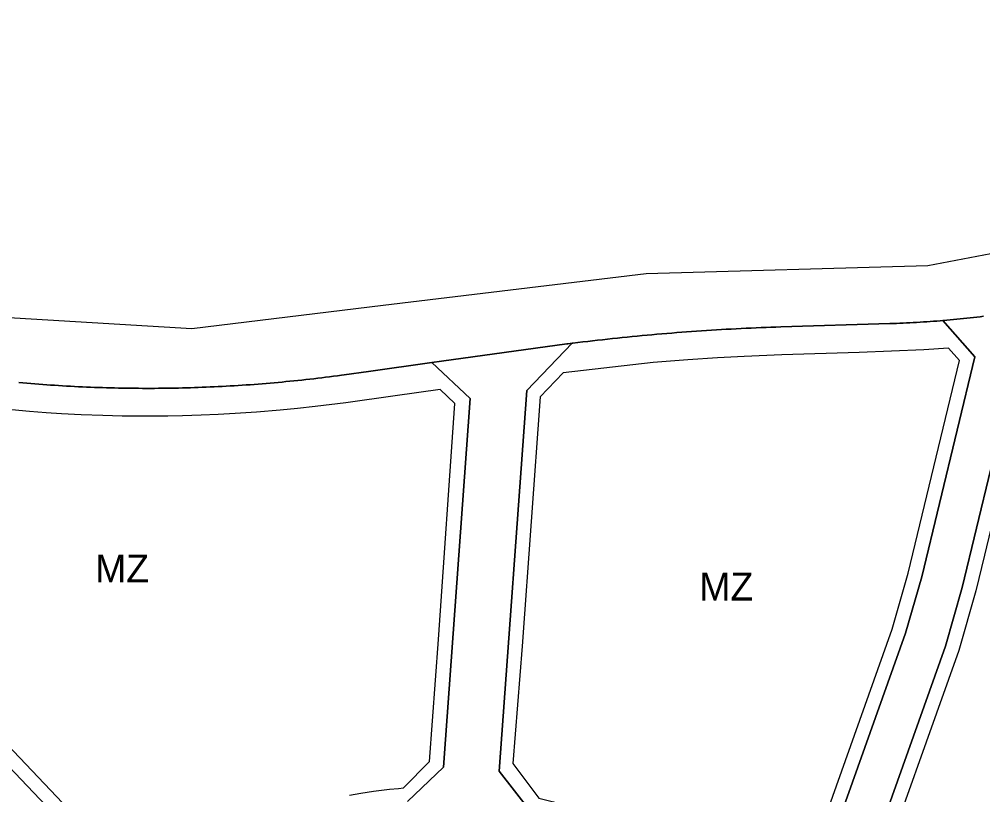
# Model space of a CAD drawing. Extents: x -297746 to -295403, y 27112 to 28877.
# Drawn here: x -297178.2 to -296833.6, y 27889.5 to 28167.1 of the extents above; entities that cross this region are included whole.
import ezdxf

# ---------------------------------------------------------------- set-up
doc = ezdxf.new("R2010")
doc.units = 0
for name, color, linetype in [('linie_rozgraniczajace', 7, 'Continuous'), ('linie_zabudowy_nieprzekraczalne', 7, 'Continuous'), ('oznaczenia_przeznaczen', 7, 'Continuous')]:
    doc.layers.add(name, color=color, linetype=linetype)

msp = doc.modelspace()

# ---------------------------------------------------------------- linework, layer by layer
at = {"layer": 'linie_rozgraniczajace'}
for points in [[(-297352.574, 28097.205), (-297275.154, 28075.397), (-297209.735, 28062.001), (-297116.494, 28056.361), (-297048.036, 28064.682), (-296954.075, 28076.102), (-296853.315, 28078.922), (-296783.197, 28092.318), (-296733.569, 28109.944), (-296648.599, 28167.051)], [(-297133.128, 27848.059), (-297348.943, 28075.477)], [(-297348.943, 28075.477), (-297133.128, 27848.059)], [(-296845.312, 28059.437), (-296846.507, 28059.33), (-296847.703, 28059.227), (-296847.897, 28059.211), (-296848.899, 28059.128), (-296850.095, 28059.033), (-296851.291, 28058.942), (-296852.488, 28058.856), (-296853.685, 28058.773), (-296854.883, 28058.694), (-296856.08, 28058.619), (-296857.278, 28058.548), (-296858.477, 28058.481), (-296859.675, 28058.418), (-296860.873, 28058.359), (-296862.072, 28058.304), (-296863.271, 28058.253), (-296864.47, 28058.206), (-296865.669, 28058.163), (-296866.869, 28058.124), (-296905.825, 28056.921), (-296907.601, 28056.864), (-296909.378, 28056.804), (-296911.154, 28056.739), (-296912.931, 28056.67), (-296914.707, 28056.597), (-296916.483, 28056.52), (-296918.259, 28056.439), (-296920.034, 28056.355), (-296921.81, 28056.266), (-296923.585, 28056.173), (-296925.36, 28056.076), (-296927.135, 28055.975), (-296928.909, 28055.871), (-296930.683, 28055.762), (-296932.458, 28055.649), (-296934.231, 28055.532), (-296936.005, 28055.412), (-296937.778, 28055.287), (-296939.551, 28055.158), (-296941.324, 28055.025), (-296943.096, 28054.889), (-296944.868, 28054.748), (-296946.64, 28054.603), (-296948.411, 28054.455), (-296950.182, 28054.302), (-296951.953, 28054.145), (-296953.724, 28053.985), (-296955.494, 28053.82), (-296957.263, 28053.651), (-296959.032, 28053.479), (-296960.801, 28053.302), (-296962.57, 28053.122), (-296964.338, 28052.937), (-296966.105, 28052.749), (-296967.873, 28052.556), (-296969.639, 28052.36), (-296971.406, 28052.159), (-296973.171, 28051.955), (-296974.937, 28051.747), (-296976.702, 28051.534), (-296978.466, 28051.318), (-296980.23, 28051.098), (-296980.47, 28051.068), (-296981.994, 28050.874), (-296982.377, 28050.824), (-297027.192, 28044.637), (-297030.725, 28044.146), (-297053.37, 28040.999), (-297062.069, 28039.791), (-297062.997, 28039.663), (-297064.412, 28039.471), (-297065.828, 28039.283), (-297067.244, 28039.098), (-297068.661, 28038.918), (-297070.079, 28038.742), (-297071.496, 28038.57), (-297072.915, 28038.402), (-297074.334, 28038.238), (-297075.753, 28038.077), (-297077.173, 28037.921), (-297078.593, 28037.769), (-297080.013, 28037.621), (-297081.434, 28037.476), (-297082.856, 28037.336), (-297084.277, 28037.2), (-297085.7, 28037.067), (-297087.122, 28036.939), (-297088.545, 28036.814), (-297089.968, 28036.694), (-297091.392, 28036.577), (-297092.815, 28036.465), (-297094.24, 28036.357), (-297095.664, 28036.252), (-297097.089, 28036.152), (-297098.514, 28036.055), (-297099.939, 28035.963), (-297101.365, 28035.874), (-297102.79, 28035.789), (-297104.216, 28035.709)], [(-296967.873, 28052.556), (-296966.105, 28052.749), (-296964.338, 28052.937), (-296962.57, 28053.122), (-296960.801, 28053.302), (-296959.032, 28053.479), (-296957.263, 28053.651), (-296955.494, 28053.82), (-296953.724, 28053.985), (-296951.953, 28054.145), (-296950.182, 28054.302), (-296948.411, 28054.455), (-296946.64, 28054.603), (-296944.868, 28054.748), (-296943.096, 28054.889), (-296941.324, 28055.025), (-296939.551, 28055.158), (-296937.778, 28055.287), (-296936.005, 28055.412), (-296934.231, 28055.532), (-296932.458, 28055.649), (-296930.683, 28055.762), (-296928.909, 28055.871), (-296927.135, 28055.975), (-296925.36, 28056.076), (-296923.585, 28056.173), (-296921.81, 28056.266), (-296920.034, 28056.355), (-296918.259, 28056.439), (-296916.483, 28056.52), (-296914.707, 28056.597), (-296912.931, 28056.67), (-296911.154, 28056.739), (-296909.378, 28056.804), (-296907.601, 28056.864), (-296905.825, 28056.921), (-296866.869, 28058.124), (-296865.669, 28058.163), (-296864.47, 28058.206), (-296863.271, 28058.253), (-296862.072, 28058.304), (-296860.873, 28058.359), (-296859.675, 28058.418), (-296858.477, 28058.481), (-296857.278, 28058.548), (-296856.08, 28058.619), (-296854.883, 28058.694), (-296853.685, 28058.773), (-296852.488, 28058.856), (-296851.291, 28058.942), (-296850.095, 28059.033), (-296848.899, 28059.128), (-296847.897, 28059.211), (-296836.494, 28046.193), (-296855.467, 27967.467), (-296861.256, 27947.303), (-296897.223, 27846.023)], [(-296897.223, 27846.023), (-296861.256, 27947.303), (-296855.467, 27967.467), (-296836.494, 28046.193), (-296847.897, 28059.211), (-296847.703, 28059.227), (-296846.507, 28059.33), (-296845.312, 28059.437), (-296844.117, 28059.548), (-296842.923, 28059.663), (-296841.728, 28059.782), (-296840.535, 28059.904), (-296839.342, 28060.031), (-296838.149, 28060.162), (-296836.956, 28060.297), (-296835.764, 28060.435), (-296834.573, 28060.578), (-296833.382, 28060.725)], [(-296833.382, 28060.725), (-296834.573, 28060.578), (-296835.764, 28060.435), (-296836.956, 28060.297), (-296838.149, 28060.162), (-296839.342, 28060.031), (-296840.535, 28059.904), (-296841.728, 28059.782), (-296842.923, 28059.663), (-296844.117, 28059.548), (-296845.312, 28059.437)], [(-297039.392, 27887.009), (-297026.524, 27899.372), (-297016.953, 28031.25), (-297030.725, 28044.146), (-297027.192, 28044.637), (-296982.377, 28050.824), (-296981.994, 28050.874), (-296980.47, 28051.068), (-296996.686, 28034.21), (-297006.58, 27897.875), (-296995.63, 27883.832)], [(-296995.63, 27883.832), (-297006.58, 27897.875), (-296996.686, 28034.21), (-296980.47, 28051.068), (-296980.23, 28051.098), (-296978.466, 28051.318), (-296976.702, 28051.534), (-296974.937, 28051.747), (-296973.171, 28051.955), (-296971.406, 28052.159), (-296969.639, 28052.36), (-296967.873, 28052.556)], [(-296820.49, 28048.576), (-296840.945, 27963.7), (-296846.998, 27942.631), (-296904.241, 27781.587), (-296903.708, 27771.365), (-296908.226, 27770.217), (-296922.224, 27766.659), (-296938.097, 27762.625)], [(-296746.59, 27811.296), (-296903.708, 27771.365), (-296904.241, 27781.587), (-296846.998, 27942.631), (-296840.945, 27963.7), (-296820.49, 28048.576)], [(-297129.911, 28034.943), (-297128.483, 28034.951), (-297127.055, 28034.964), (-297125.627, 28034.981), (-297124.199, 28035.001), (-297122.771, 28035.026), (-297121.343, 28035.054), (-297119.915, 28035.087), (-297118.487, 28035.123), (-297117.059, 28035.164), (-297115.632, 28035.209), (-297114.204, 28035.257), (-297112.777, 28035.31), (-297111.35, 28035.366), (-297109.923, 28035.427), (-297108.496, 28035.491), (-297107.069, 28035.56), (-297105.643, 28035.632), (-297104.216, 28035.709), (-297102.79, 28035.789), (-297101.365, 28035.874), (-297099.939, 28035.963), (-297098.514, 28036.055), (-297097.089, 28036.152), (-297095.664, 28036.252), (-297094.24, 28036.357), (-297092.815, 28036.465), (-297091.392, 28036.577), (-297089.968, 28036.694), (-297088.545, 28036.814), (-297087.122, 28036.939), (-297085.7, 28037.067), (-297084.277, 28037.2), (-297082.856, 28037.336), (-297081.434, 28037.476), (-297080.013, 28037.621), (-297078.593, 28037.769), (-297077.173, 28037.921), (-297075.753, 28038.077), (-297074.334, 28038.238), (-297072.915, 28038.402), (-297071.496, 28038.57), (-297070.079, 28038.742), (-297068.661, 28038.918), (-297067.244, 28039.098), (-297065.828, 28039.283), (-297064.412, 28039.471), (-297062.997, 28039.663), (-297062.069, 28039.791), (-297053.37, 28040.999), (-297030.725, 28044.146), (-297016.953, 28031.25), (-297026.524, 27899.372), (-297039.392, 27887.009)], [(-297131.34, 28034.938), (-297132.768, 28034.938), (-297134.196, 28034.941), (-297135.625, 28034.948), (-297137.053, 28034.96), (-297138.481, 28034.975), (-297139.909, 28034.995), (-297141.337, 28035.018), (-297142.765, 28035.046), (-297144.193, 28035.077), (-297145.621, 28035.112), (-297147.049, 28035.152), (-297148.476, 28035.195), (-297149.904, 28035.243), (-297151.331, 28035.294), (-297152.758, 28035.35), (-297154.186, 28035.409), (-297155.612, 28035.472), (-297157.039, 28035.54), (-297158.466, 28035.611), (-297159.892, 28035.686), (-297161.318, 28035.766), (-297162.744, 28035.849), (-297164.169, 28035.937), (-297165.595, 28036.028), (-297167.02, 28036.123), (-297168.445, 28036.223), (-297169.869, 28036.326), (-297171.294, 28036.433), (-297172.717, 28036.545), (-297174.141, 28036.66), (-297175.564, 28036.779), (-297176.987, 28036.903), (-297178.41, 28037.03)], [(-297178.41, 28037.03), (-297176.987, 28036.903), (-297175.564, 28036.779), (-297174.141, 28036.66), (-297172.717, 28036.545), (-297171.294, 28036.433), (-297169.869, 28036.326), (-297168.445, 28036.223), (-297167.02, 28036.123), (-297165.595, 28036.028), (-297164.169, 28035.937), (-297162.744, 28035.849), (-297161.318, 28035.766), (-297159.892, 28035.686), (-297158.466, 28035.611), (-297157.039, 28035.54), (-297155.612, 28035.472), (-297154.186, 28035.409), (-297152.758, 28035.35), (-297151.331, 28035.294), (-297149.904, 28035.243), (-297148.476, 28035.195), (-297147.049, 28035.152), (-297145.621, 28035.112), (-297144.193, 28035.077), (-297142.765, 28035.046), (-297141.337, 28035.018), (-297139.909, 28034.995), (-297138.481, 28034.975), (-297137.053, 28034.96), (-297135.625, 28034.948), (-297134.196, 28034.941), (-297132.768, 28034.938), (-297131.34, 28034.938), (-297129.911, 28034.943)], [(-297104.216, 28035.709), (-297105.643, 28035.632), (-297107.069, 28035.56), (-297108.496, 28035.491), (-297109.923, 28035.427), (-297111.35, 28035.366), (-297112.777, 28035.31), (-297114.204, 28035.257), (-297115.632, 28035.209), (-297117.059, 28035.164), (-297118.487, 28035.123), (-297119.915, 28035.087), (-297121.343, 28035.054), (-297122.771, 28035.026), (-297124.199, 28035.001), (-297125.627, 28034.981), (-297127.055, 28034.964), (-297128.483, 28034.951), (-297129.911, 28034.943), (-297131.34, 28034.938)]]:
    msp.add_lwpolyline(points, dxfattribs=at)
at = {"layer": 'linie_zabudowy_nieprzekraczalne'}
for points in [[(-296851.976, 27789.673), (-296824.597, 27796.631), (-296797.958, 27803.401), (-296749.499, 27815.717), (-296741.777, 27825.783), (-296742.434, 27875.778), (-296742.755, 27900.235), (-296743.74, 27975.234), (-296744.353, 28021.948), (-296745.685, 28072.411), (-296758.138, 28067.897), (-296770.384, 28063.942), (-296781.847, 28060.666), (-296793.481, 28057.73), (-296802.375, 28055.778), (-296811.307, 28054.009), (-296814.968, 28050.135), (-296833.03, 27975.191), (-296836.107, 27962.425), (-296842.232, 27941.104), (-296873.517, 27853.087), (-296883.689, 27824.469)], [(-297326.341, 28058.929), (-297167.124, 27891.151)], [(-297326.341, 28058.929), (-297167.124, 27891.151)], [(-296889.201, 27883.549), (-296866.059, 27948.685), (-296860.299, 27968.745), (-296841.958, 28044.848), (-296845.929, 28049.381), (-296854.699, 28048.687), (-296877.816, 28047.783), (-296905.513, 28046.928), (-296918.975, 28046.396), (-296928.537, 28045.877), (-296939.143, 28045.163), (-296951.52, 28044.146), (-296983.681, 28040.516), (-296991.91, 28031.961)], [(-297028.274, 27945.054), (-297022.422, 28029.525), (-297027.703, 28034.471), (-297027.703, 28034.471), (-297043.75, 28032.241), (-297061.478, 28029.779), (-297072.373, 28028.399), (-297078.722, 28027.702), (-297084.922, 28027.098), (-297093.382, 28026.395), (-297101.014, 28025.879), (-297107.124, 28025.547), (-297113.229, 28025.288), (-297119.835, 28025.088), (-297125.138, 28024.988), (-297132.658, 28024.94), (-297141.421, 28025.02), (-297148.343, 28025.188), (-297156.124, 28025.487), (-297163.115, 28025.856), (-297168.67, 28026.216), (-297174.593, 28026.666), (-297180.884, 28027.218)], [(-296991.91, 28031.961), (-296998.373, 27942.607)], [(-297060.104, 27889.293), (-297056.078, 27890.034), (-297051.594, 27890.739), (-297045.841, 27891.458), (-297042.661, 27891.767), (-297040.858, 27891.905), (-297031.578, 27901.317), (-297028.274, 27945.054)], [(-296998.373, 27942.607), (-297001.702, 27900.64), (-296992.428, 27888.215), (-296987.207, 27886.934), (-296976.284, 27883.612), (-296968.152, 27880.588), (-296961.386, 27877.691), (-296950.599, 27872.302), (-296942.132, 27867.334), (-296934.129, 27861.957), (-296924.334, 27854.385), (-296914.487, 27845.474), (-296914.487, 27845.474), (-296901.324, 27849.422), (-296889.201, 27883.549)], [(-297167.124, 27891.151), (-297132.706, 27854.883)]]:
    msp.add_lwpolyline(points, dxfattribs=at)

# ---------------------------------------------------------------- texts
at = {"layer": 'oznaczenia_przeznaczen'}
for p in [(-297151.124, 27965.454), (-296935.013, 27958.997)]:
    msp.add_text('MZ', height=10, dxfattribs=at).set_placement(p)

doc.saveas('drawing.dxf')
